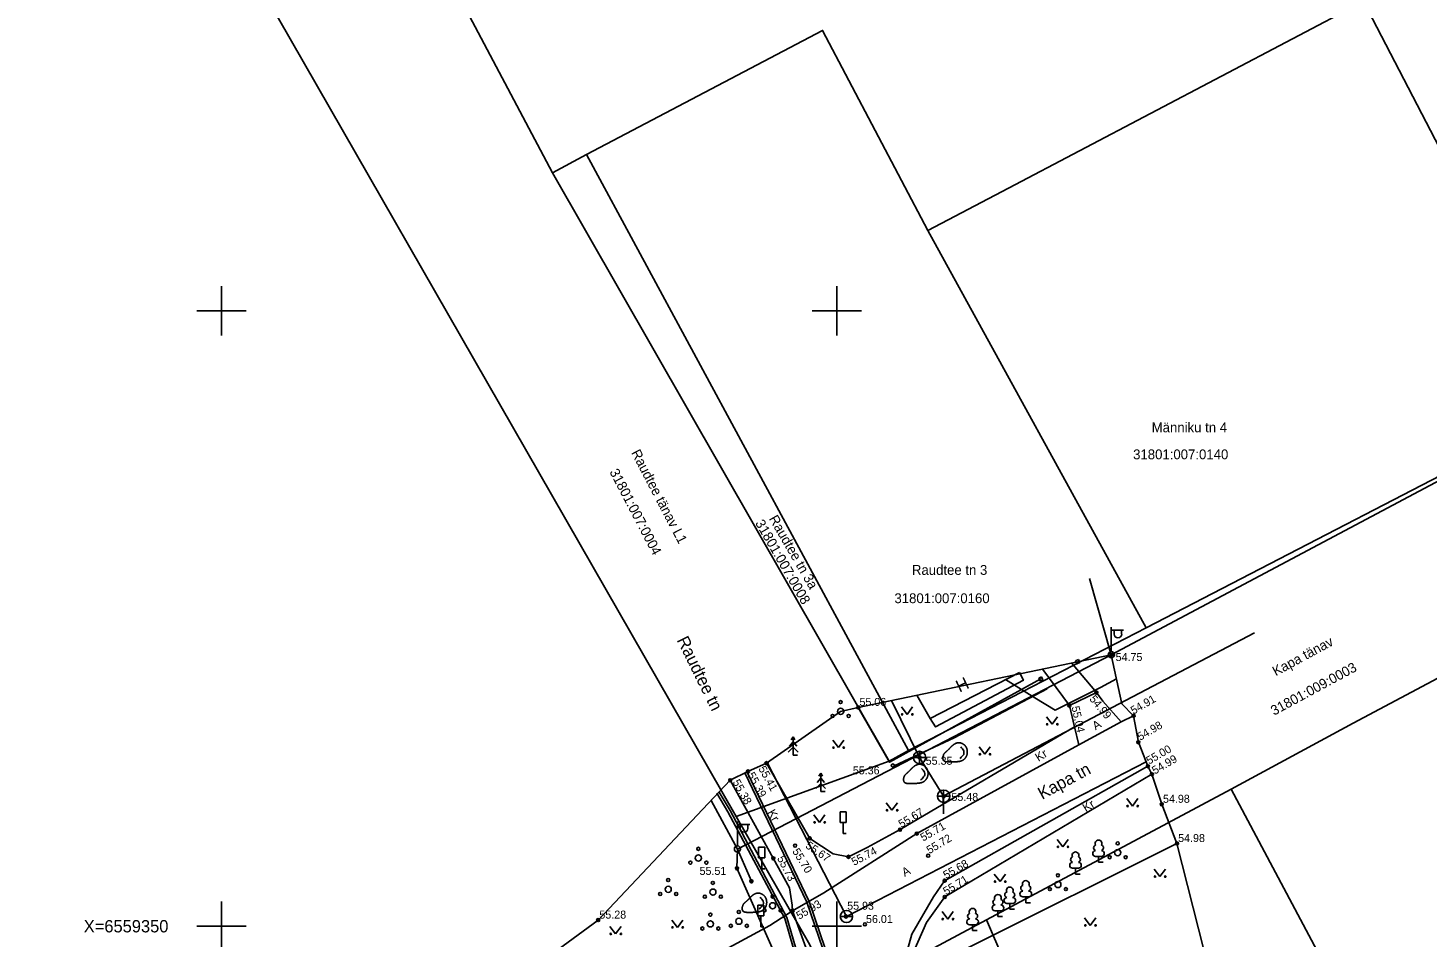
# Model space of a CAD drawing. Extents: x 542320 to 543602, y 6558748 to 6559969.
# Drawn here: x 542534.3 to 542647.9, y 6559349.1 to 6559423 of the extents above; entities that cross this region are included whole.
import ezdxf

# ---------------------------------------------------------------- set-up
doc = ezdxf.new("R2010")
doc.units = 0
for name, color, linetype in [('AED', 7, 'Continuous'), ('HALJASTUS', 7, 'Continuous'), ('HOONE', 7, 'Continuous'), ('KKAEV', 7, 'Continuous'), ('KORGUS-EH2000', 7, 'Continuous'), ('KPKAABEL', 7, 'Continuous'), ('KTRASS', 7, 'Continuous'), ('LIIKLUS', 7, 'Continuous'), ('mootpiir', 7, 'Continuous'), ('MPKAABEL', 7, 'Continuous'), ('MPOHULIIN', 7, 'Continuous'), ('PIIR', 7, 'Continuous'), ('POST', 7, 'Continuous'), ('PUU', 7, 'Continuous'), ('RELJEEF', 7, 'Continuous'), ('SITRASS', 7, 'Continuous'), ('TEE', 7, 'Continuous'), ('VKAEV', 7, 'Continuous'), ('VORK', 7, 'Continuous'), ('VTRASS', 7, 'Continuous')]:
    doc.layers.add(name, color=color, linetype=linetype)

# ---------------------------------------------------------------- blocks, each defined once
blk = doc.blocks.new('VKORIS')
for p, q in [((0, 4), (0, -4)), ((-4, 0), (4, 0))]:
    blk.add_line(p, q)
blk = doc.blocks.new('VEKAEV')
blk.add_line((-1, 0), (1, 0))
blk.add_circle((0, 0), 1)
blk = doc.blocks.new('KAKAEV')
for p, q in [((-1, 0), (1, 0)), ((0, -1), (0, 1))]:
    blk.add_line(p, q)
blk.add_circle((0, 0), 1)
blk = doc.blocks.new('PQQSAS')
for centre, radius in [((0, 0), 0.5), ((0, 1.5), 0.25), ((-1.3, -0.75), 0.25), ((1.3, -0.75), 0.25)]:
    blk.add_circle(centre, radius)
blk = doc.blocks.new('LEHTP1')
for p, q in [((0.48, 0.95), (-0.48, 0.95)), ((0, 0), (0, 0.95)), ((0.76, 0), (0, 0))]:
    blk.add_line(p, q)
for centre, radius, start, end in [((-0.34, 2.35), 0.465, 109.0217, 253.1415), ((0, 3.04), 0.554, 332.5799, 207.4201), ((0.34, 2.35), 0.465, 286.8508, 70.9859), ((-0.47, 1.42), 0.475, 90.0016, 269.3953), ((0.47, 1.42), 0.475, 270.6047, 89.9984)]:
    blk.add_arc(centre, radius, start, end)
blk = doc.blocks.new('KUUSK1')
for p, q in [((0, 3), (-0.3, 2.5)), ((0.3, 2.5), (0, 3)), ((0, 3), (0, 0)), ((0, 1.3), (-0.8, 0.5)), ((0, 2.2), (-0.6, 1.5)), ((0.6, 1.5), (0, 2.2)), ((0.8, 0.5), (0, 1.3)), ((0.72, 0), (0, 0))]:
    blk.add_line(p, q)
blk = doc.blocks.new('ANKURP')
for radius in [0.25, 0.234, 0.219, 0.203, 0.188, 0.172, 0.156, 0.141, 0.125, 0.11, 0.0939, 0.0783, 0.0628, 0.0472, 0.0316, 0.016, 0.000371]:
    blk.add_circle((0, 0), radius)
blk = doc.blocks.new('PUPOST')
blk.add_circle((0, 0), 0.5)
blk = doc.blocks.new('VAPOST')
for p, q in [((0, 0.5), (0, 4.5)), ((0, 4), (2, 4)), ((0.45, 3.36), (0.45, 4)), ((1.68, 3.36), (1.68, 4))]:
    blk.add_line(p, q)
blk.add_arc((1.07, 3.36), 0.613, 180, 0)
blk = doc.blocks.new('KIVISU')
blk.add_lwpolyline([(0.72, -0.83), (0.81, -0.74), (0.94, -0.59), (1.08, -0.45), (1.21, -0.3), (1.33, -0.14), (1.38, 0.06), (1.38, 0.26), (1.33, 0.45), (1.25, 0.63), (1.12, 0.79), (0.99, 0.94), (0.86, 1.09)])
blk.add_open_spline([(-2.05, -0.57), (-2.05, -0.57), (-2.04, -1.09), (-1.65, -1.35), (-1.15, -1.37), (-0.65, -1.37), (-0.15, -1.36), (0.35, -1.32), (0.84, -1.25), (1.29, -1.05), (1.64, -0.69), (1.87, -0.25), (1.94, 0.24), (1.88, 0.74), (1.67, 1.19), (1.31, 1.53), (0.85, 1.74), (0.36, 1.78), (-0.1, 1.59), (-0.51, 1.3), (-0.86, 0.94), (-1.2, 0.58), (-1.58, 0.25), (-1.94, -0.08), (-2.05, -0.57)], degree=2)
blk = doc.blocks.new('LIIKLM')
for points in [[(-0.5, 3.5), (-0.5, 1.8)], [(0.5, 3.5), (-0.5, 3.5)], [(0.5, 3.5), (0.5, 1.8)], [(0.5, 1.8), (-0.5, 1.8)], [(0, 1.8), (0, 0)], [(0.5, 0), (0, 0)]]:
    blk.add_lwpolyline(points)
blk = doc.blocks.new('VARPOS')
for p, q in [((-0.25, 0.25), (-0.25, -0.25)), ((-0.25, 0.25), (0.25, 0.25)), ((0.25, 0.25), (0.25, -0.25)), ((-0.25, -0.25), (0.25, -0.25))]:
    blk.add_line(p, q)
blk = doc.blocks.new('MURU')
for p, q in [((-0.93, 1.21), (0, 0)), ((0, 0), (0.89, 1.21))]:
    blk.add_line(p, q)
for centre in [(-0.8, 0), (0.86, 0)]:
    blk.add_circle(centre, 0.11)
blk = doc.blocks.new('RING02')
blk.add_circle((0, 0), 0.25)

msp = doc.modelspace()

# ---------------------------------------------------------------- linework, layer by layer
at = {"layer": 'AED'}
msp.add_lwpolyline([(542616.56, 6559370.09), (542616.56, 6559370.09), (542604.27, 6559363.33), (542601.73, 6559367.78)], dxfattribs=at)
at = {"layer": 'HALJASTUS'}
for points in [[(542617.07, 6559369.28), (542609.51, 6559365.3), (542604.64, 6559363.02)], [(542610.68, 6559348.26), (542627.62, 6559356.73)]]:
    msp.add_lwpolyline(points, dxfattribs=at)
at = {"layer": 'HOONE'}
for points in [[(542607.58, 6559366.89), (542614.83, 6559370.62)], [(542607.58, 6559366.89), (542606.48, 6559368.77)]]:
    msp.add_lwpolyline(points, dxfattribs=at)
at = {"layer": 'KPKAABEL'}
for points in [[(542592.52, 6559362.45), (542597.55, 6559351.95), (542600.14, 6559344.37), (542606.12, 6559332.4), (542610.86, 6559323.16), (542616.27, 6559312.94), (542622.06, 6559301.81), (542626.97, 6559292.38), (542631.61, 6559283.75), (542633.96, 6559279.16), (542635.84, 6559275.61), (542642.33, 6559262.55)], [(542592.7, 6559362.53), (542597.73, 6559352.02), (542600.32, 6559344.44), (542606.3, 6559332.49), (542611.03, 6559323.25), (542616.45, 6559313.04), (542622.24, 6559301.9), (542627.15, 6559292.48), (542631.79, 6559283.85), (542634.14, 6559279.25), (542636.01, 6559275.7), (542642.5, 6559262.64)], [(542629.71, 6559255.55), (542624.46, 6559265.01), (542621.33, 6559279), (542619.56, 6559289.35), (542615.6, 6559299.12), (542610.38, 6559310.03), (542605.39, 6559319.87), (542600.37, 6559330.02), (542596.98, 6559338.2), (542596.38, 6559342.12), (542596.81, 6559346.97), (542595.76, 6559350.64), (542591.14, 6559359.29), (542590.25, 6559360.8)], [(542629.88, 6559255.64), (542624.65, 6559265.09), (542621.53, 6559279.04), (542619.76, 6559289.41), (542615.79, 6559299.2), (542610.56, 6559310.12), (542605.57, 6559319.96), (542600.55, 6559330.11), (542597.18, 6559338.25), (542596.58, 6559342.13), (542597.01, 6559346.99), (542595.94, 6559350.72), (542591.32, 6559359.39), (542590.42, 6559360.9)]]:
    msp.add_lwpolyline(points, dxfattribs=at)
at = {"layer": 'KTRASS'}
for points in [[(542633.92, 6559373.83), (542608.64, 6559360.58)], [(542606.71, 6559363.72), (542604.42, 6559368.34)], [(542606.71, 6559363.72), (542608.67, 6559360.56)], [(542608.64, 6559360.58), (542608.65, 6559359.13)]]:
    msp.add_lwpolyline(points, dxfattribs=at)
at = {"layer": 'mootpiir'}
msp.add_lwpolyline([(542636.85, 6559320.34), (542627.62, 6559356.73), (542626.39, 6559359.91), (542625.59, 6559362.35), (542625.26, 6559363), (542624.49, 6559364.95), (542624.1, 6559367.1), (542623.15, 6559368.08), (542622.29, 6559372.06), (542601.73, 6559367.78), (542600.3, 6559367.46), (542594.28, 6559363.25), (542592.77, 6559362.57), (542591.33, 6559361.86), (542580.6, 6559350.5), (542576.13, 6559347.21)], dxfattribs=at)
at = {"layer": 'MPKAABEL'}
msp.add_lwpolyline([(542595.26, 6559347.08), (542591.88, 6559354.71), (542591.92, 6559356.27)], dxfattribs=at)
at = {"layer": 'MPOHULIIN'}
for points in [[(542661.99, 6559393.16), (542622.29, 6559372.06), (542620.51, 6559378.26)], [(542622.29, 6559372.06), (542591.92, 6559356.27), (542589.78, 6559360.22)]]:
    msp.add_lwpolyline(points, dxfattribs=at)
at = {"layer": 'PIIR'}
for points in [[(542456.68, 6559581.07), (542523.83, 6559477.46), (542537.52, 6559453.62), (542591.81, 6559358.92), (542597.79, 6559348.5), (542599.76, 6559343.89), (542619.08, 6559298.96), (542624.28, 6559266.08), (542637.46, 6559233.17), (542680, 6559143.81), (542700.43, 6559093.84), (542700.92, 6559090.29), (542704.02, 6559067.82)], [(542537.52, 6559453.62), (542551.09, 6559459.97), (542576.89, 6559411.22), (542604.23, 6559363.42), (542591.81, 6559358.92), (542537.52, 6559453.62)], [(542741.15, 6559419.37), (542715.89, 6559405.45), (542681.21, 6559386.88), (542667.3, 6559379.98), (542641.94, 6559366.51), (542632.02, 6559361.13), (542612.16, 6559350.51), (542599.76, 6559343.89), (542597.79, 6559348.5), (542591.81, 6559358.92), (542604.23, 6559363.42), (542605.82, 6559364.28), (542625.12, 6559374.24), (542659.87, 6559392.24), (542673.76, 6559400.37), (542691.07, 6559409.58), (542708.69, 6559418.93), (542715.22, 6559422.45), (542743.96, 6559437.79)], [(542607.38, 6559406.52), (542613.93, 6559409.96), (542642.79, 6559425.13), (542659.87, 6559392.24), (542625.12, 6559374.24), (542607.38, 6559406.52)], [(542579.66, 6559412.7), (542598.83, 6559422.78), (542607.38, 6559406.52), (542625.12, 6559374.24), (542605.82, 6559364.28), (542579.66, 6559412.7)], [(542604.23, 6559363.42), (542576.89, 6559411.22), (542579.66, 6559412.7), (542605.82, 6559364.28), (542604.23, 6559363.42)], [(542632.02, 6559361.13), (542641.94, 6559366.51), (542667.3, 6559379.98), (542686.87, 6559343.19), (542661.3, 6559329.57), (542651.63, 6559324.28), (542632.02, 6559361.13)], [(542632.63, 6559302.87), (542612.16, 6559350.51), (542632.02, 6559361.13), (542651.63, 6559324.28), (542646.33, 6559321.44), (542665.85, 6559284.72), (542671.39, 6559287.65), (542689.34, 6559253.48), (542704.9, 6559215.47), (542674.63, 6559203.23), (542672.45, 6559208.6), (542665.71, 6559205.86), (542632.63, 6559302.87)], [(542612.16, 6559350.51), (542632.63, 6559302.87), (542665.71, 6559205.86), (542667.87, 6559200.49), (542682.31, 6559164.31), (542683.94, 6559160.9), (542699.54, 6559124.27), (542718.47, 6559078.4), (542700.92, 6559090.29), (542700.43, 6559093.84), (542680, 6559143.81), (542637.46, 6559233.17), (542624.28, 6559266.08), (542619.08, 6559298.96), (542599.76, 6559343.89), (542612.16, 6559350.51)]]:
    msp.add_lwpolyline(points, dxfattribs=at)
at = {"layer": 'POST'}
msp.add_lwpolyline([(542593.05, 6559353.65), (542591.92, 6559356.27)], dxfattribs=at)
at = {"layer": 'SITRASS'}
msp.add_lwpolyline([(542622.71, 6559370.1), (542621.4, 6559369.4), (542617.72, 6559367.56), (542616.07, 6559368.56), (542613.7, 6559370.04)], dxfattribs=at)
at = {"layer": 'TEE'}
for points in [[(542618.88, 6559367.93), (542616.72, 6559370.87)], [(542621.08, 6559368.98), (542619.06, 6559371.41)], [(542607.58, 6559366.89), (542608.01, 6559366.19), (542615.15, 6559369.98), (542614.83, 6559370.62)], [(542623.09, 6559366.62), (542621.59, 6559368.29), (542621.08, 6559368.98), (542618.88, 6559367.93), (542619.31, 6559366.2), (542619.66, 6559364.74)], [(542619.31, 6559366.2), (542605.13, 6559357.85), (542602.45, 6559356.4), (542600.94, 6559355.64), (542599.68, 6559355.89), (542597.79, 6559357.14), (542594.28, 6559363.25)], [(542624.1, 6559367.1), (542623.09, 6559366.62), (542619.66, 6559364.74), (542606.49, 6559357.53), (542598.93, 6559352.72), (542596.39, 6559351.26), (542597.48, 6559348.27), (542599.1, 6559344.51), (542601.52, 6559338.8), (542604.02, 6559333.45), (542609.84, 6559322.48), (542616.48, 6559310.11), (542621.37, 6559299.41), (542623.15, 6559294.6), (542623.73, 6559292.74), (542624.33, 6559289.25), (542624.92, 6559285.03), (542624.92, 6559280.09), (542625.11, 6559275.88), (542626.16, 6559270.71), (542630.82, 6559257.34)], [(542634.68, 6559258.87), (542630.15, 6559271.92), (542629.13, 6559276.41), (542628.98, 6559278.99), (542628.99, 6559283.21), (542628.79, 6559287.96), (542628.21, 6559291.8), (542627.22, 6559295.85), (542627.15, 6559296.26), (542626, 6559299.92), (542624.09, 6559304.14), (542620.26, 6559312.26), (542613.87, 6559324.5), (542608.18, 6559335.16), (542606.43, 6559338.99), (542605.72, 6559341.19), (542605.4, 6559342.93), (542605.27, 6559345.1), (542605.47, 6559347.12), (542606.08, 6559349.35), (542607.84, 6559352.39), (542608.75, 6559353.7), (542625.26, 6559363)], [(542591.33, 6559361.86), (542594.83, 6559355.52), (542596.14, 6559353.12), (542596.36, 6559351.72), (542596.39, 6559351.26)], [(542625.59, 6559362.35), (542608.76, 6559352.38), (542607.28, 6559350.3), (542606.17, 6559347.79), (542605.93, 6559345.3), (542606.43, 6559342.48), (542606.99, 6559340.5), (542609.2, 6559335.67), (542614.6, 6559324.83), (542620.94, 6559312.64), (542624.6, 6559304.52), (542626.86, 6559298.57), (542627.69, 6559295.96), (542628.38, 6559292.61), (542629.03, 6559288.15), (542629.33, 6559283.8), (542629.22, 6559279.54), (542629.4, 6559276.51), (542629.82, 6559274.79), (542630.58, 6559272.19), (542635.47, 6559259.16)], [(542596.39, 6559351.26), (542594.54, 6559350.06), (542583.59, 6559344.12), (542576.24, 6559340.02), (542575.15, 6559339.14)]]:
    msp.add_lwpolyline(points, dxfattribs=at)
at = {"layer": 'VTRASS'}
msp.add_lwpolyline([(542625.12, 6559363.35), (542600.77, 6559350.79), (542594.33, 6559363.29)], dxfattribs=at)

# ---------------------------------------------------------------- block references
at = {"layer": 'AED', "xscale": 0.5, "yscale": 0.5, "rotation": -64.31337135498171}
for p in [(542619.56, 6559371.5), (542616.56, 6559370.09)]:
    msp.add_blockref('VARPOS', p, dxfattribs=at)
at = {"layer": 'HALJASTUS', "xscale": 0.5, "yscale": 0.5}
for name, p in [('MURU', (542605.7, 6559367.21)), ('MURU', (542617.48, 6559366.41)), ('MURU', (542600.12, 6559364.52)), ('MURU', (542612.01, 6559363.97)), ('MURU', (542604.47, 6559359.42)), ('MURU', (542624.01, 6559359.76)), ('MURU', (542598.58, 6559358.44)), ('PQQSAS', (542588.74, 6559355.54)), ('MURU', (542618.35, 6559356.45)), ('PQQSAS', (542586.29, 6559353)), ('MURU', (542613.25, 6559353.63)), ('MURU', (542626.24, 6559354.03)), ('PQQSAS', (542589.92, 6559352.77)), ('PQQSAS', (542594.77, 6559351.66)), ('MURU', (542587.04, 6559349.9)), ('PQQSAS', (542589.72, 6559350.19)), ('PQQSAS', (542592.03, 6559350.41)), ('MURU', (542609, 6559350.58)), ('MURU', (542620.58, 6559350.07)), ('MURU', (542582.02, 6559349.38))]:
    msp.add_blockref(name, p, dxfattribs=at)
at = {"layer": 'KKAEV', "xscale": 0.5, "yscale": 0.5}
for p in [(542606.71, 6559363.72), (542608.67, 6559360.56)]:
    msp.add_blockref('KAKAEV', p, dxfattribs=at)
at = {"layer": 'KORGUS-EH2000', "xscale": 0.5, "yscale": 0.5}
for p in [(542622.29, 6559372.06), (542621.08, 6559368.98), (542601.73, 6559367.78), (542618.88, 6559367.93), (542624.1, 6559367.1), (542624.49, 6559364.95), (542594.28, 6559363.25), (542604.54, 6559363.06), (542606.71, 6559363.72), (542625.26, 6559363), (542591.33, 6559361.86), (542592.77, 6559362.57), (542625.59, 6559362.35), (542608.67, 6559360.56), (542626.39, 6559359.91), (542597.79, 6559357.14), (542605.13, 6559357.85), (542606.49, 6559357.53), (542596.6, 6559356.55), (542627.62, 6559356.73), (542591.88, 6559354.71), (542594.83, 6559355.52), (542600.94, 6559355.64), (542607.41, 6559355.73), (542608.75, 6559353.7), (542596.39, 6559351.26), (542608.76, 6559352.38), (542580.6, 6559350.5), (542600.74, 6559350.79), (542602.27, 6559350.15)]:
    msp.add_blockref('RING02', p, dxfattribs=at)
at = {"layer": 'LIIKLUS', "xscale": 0.5, "yscale": 0.5}
for p in [(542600.51, 6559357.54), (542593.89, 6559354.67), (542593.81, 6559349.95)]:
    msp.add_blockref('LIIKLM', p, dxfattribs=at)
at = {"layer": 'POST', "xscale": 0.5, "yscale": 0.5}
for name, p in [('VAPOST', (542622.29, 6559372.06)), ('PUPOST', (542622.29, 6559372.06)), ('VAPOST', (542591.92, 6559356.27)), ('PUPOST', (542591.92, 6559356.27)), ('ANKURP', (542593.05, 6559353.65))]:
    msp.add_blockref(name, p, dxfattribs=at)
at = {"layer": 'PUU', "xscale": 0.5, "yscale": 0.5}
for name, p in [('PQQSAS', (542600.3, 6559367.46)), ('KUUSK1', (542596.44, 6559363.89)), ('KUUSK1', (542598.68, 6559360.94)), ('LEHTP1', (542619.38, 6559354.24)), ('LEHTP1', (542621.25, 6559355.2)), ('PQQSAS', (542622.81, 6559355.98)), ('LEHTP1', (542615.34, 6559351.91)), ('PQQSAS', (542617.95, 6559353.39)), ('LEHTP1', (542613.08, 6559350.78)), ('LEHTP1', (542614.04, 6559351.38)), ('LEHTP1', (542611.02, 6559349.65))]:
    msp.add_blockref(name, p, dxfattribs=at)
at = {"layer": 'RELJEEF', "xscale": 0.5, "yscale": 0.5}
for p in [(542609.63, 6559364.03), (542606.44, 6559362.28), (542593.33, 6559351.81)]:
    msp.add_blockref('KIVISU', p, dxfattribs=at)
at = {"layer": 'VKAEV', "xscale": 0.5, "yscale": 0.5}
msp.add_blockref('VEKAEV', (542600.77, 6559350.79), dxfattribs=at)
at = {"layer": 'VORK', "xscale": 0.5, "yscale": 0.5}
for p in [(542550, 6559400), (542600, 6559400), (542550, 6559350), (542600, 6559350)]:
    msp.add_blockref('VKORIS', p, dxfattribs=at)

# ---------------------------------------------------------------- texts
at = {"layer": 'HOONE'}
msp.add_text('H', height=1, rotation=25.5167, dxfattribs=at).set_placement((542609.96, 6559368.97))
at = {"layer": 'KORGUS-EH2000'}
for s, p in [('54.75', (542622.64, 6559371.55)), ('55.06', (542601.83, 6559367.9)), ('55.36', (542601.29, 6559362.34)), ('55.35', (542607.21, 6559363.12)), ('55.48', (542609.3, 6559360.18)), ('54.98', (542626.49, 6559360.03)), ('54.98', (542627.72, 6559356.84)), ('55.51', (542588.84, 6559354.17)), ('55.93', (542600.83, 6559351.34)), ('55.28', (542580.7, 6559350.62)), ('56.01', (542602.36, 6559350.26))]:
    msp.add_text(s, height=0.65, dxfattribs=at).set_placement(p)
for s, rotation, p in [('54.99', 309.7101, (542620.47, 6559368.44)), ('54.91', 30.1105, (542624.09, 6559367.19)), ('55.04', 282.6154, (542619.05, 6559367.81)), ('54.98', 30.1105, (542624.63, 6559365.06)), ('55.00', 30.1105, (542625.36, 6559363.12)), ('54.99', 30.1105, (542625.83, 6559362.32)), ('55.41', 298.8576, (542593.6, 6559362.81)), ('55.38', 298.8576, (542591.5, 6559361.71)), ('55.39', 298.8576, (542592.7, 6559362.3)), ('55.67', 30.9044, (542605.24, 6559357.97)), ('55.71', 29.7681, (542607, 6559356.87)), ('55.72', 31.0976, (542607.52, 6559355.85)), ('55.70', 301.4491, (542596.35, 6559356.09)), ('55.67', 325.7, (542597.39, 6559356.41)), ('55.74', 27.7544, (542601.39, 6559354.9)), ('55.73', 297.1474, (542595.12, 6559355.52)), ('55.68', 29.5814, (542608.86, 6559353.82)), ('55.71', 31.4084, (542608.87, 6559352.5)), ('55.93', 30.4694, (542596.93, 6559350.52))]:
    msp.add_text(s, height=0.65, rotation=rotation, dxfattribs=at).set_placement(p)
at = {"layer": 'PIIR'}
for s, p in [('Männiku tn 4', (542625.57, 6559390.13)), ('31801:007:0140', (542624.06, 6559387.94)), ('Raudtee tn 3', (542606.09, 6559378.55)), ('31801:007:0160', (542604.67, 6559376.25))]:
    msp.add_text(s, height=0.8, dxfattribs=at).set_placement(p)
for s, rotation, p in [('Raudtee tänav L1', 297.5454, (542583.26, 6559388.48)), ('31801:007:0004', 297.5454, (542581.5, 6559386.92)), ('Raudtee tn 3a', 299.9989, (542594.45, 6559383.12)), ('31801:007:0008', 299.9989, (542593.33, 6559382.76)), ('Kapa tänav', 28.4418, (542635.65, 6559370.3)), ('31801:009:0003', 28.4418, (542635.51, 6559367.1))]:
    msp.add_text(s, height=0.8, rotation=rotation, dxfattribs=at).set_placement(p)
at = {"layer": 'TEE'}
for s, height, rotation, p in [('Raudtee tn', 1, 296.2149, (542586.97, 6559373.26)), ('A', 0.7, 31.6874, (542621.01, 6559365.9)), ('Kr', 0.7, 31.6874, (542616.37, 6559363.35)), ('Kapa tn', 1, 28.4437, (542616.67, 6559360.26)), ('Kr', 0.7, 299.4082, (542594.32, 6559359.25)), ('Kr', 0.7, 31.6874, (542620.22, 6559359.25)), ('A', 0.7, 28.2532, (542605.5, 6559354))]:
    msp.add_text(s, height=height, rotation=rotation, dxfattribs=at).set_placement(p)
at = {"layer": 'VORK'}
msp.add_text('X=6559350', height=1, dxfattribs=at).set_placement((542538.81, 6559349.5))

doc.saveas('drawing.dxf')
